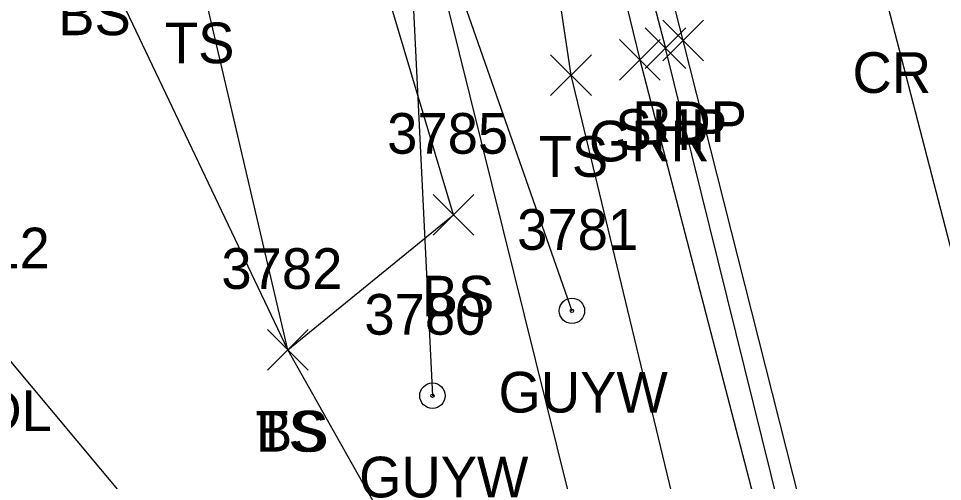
# Model space of a CAD drawing. Extents: x 1601151 to 1602912, y 499508 to 501770.
# Drawn here: x 1601576.97 to 1601622.39, y 500514.77 to 500537.54 of the extents above; entities that cross this region are included whole.
import ezdxf

# ---------------------------------------------------------------- set-up
doc = ezdxf.new("R2010")
doc.units = 0
for name, color, linetype in [('L_A', 7, 'Continuous'), ('L_I', 7, 'Continuous'), ('L_TIC', 7, 'Continuous'), ('LELB', 7, 'Continuous'), ('P_A', 7, 'Continuous'), ('P_TIC', 7, 'Continuous'), ('PET', 7, 'Continuous'), ('PRC', 7, 'Continuous'), ('PSP', 7, 'Continuous'), ('R_A', 7, 'Continuous'), ('R_TIC', 7, 'Continuous'), ('RGR', 7, 'Continuous'), ('U_A', 7, 'Continuous'), ('U_I', 7, 'Continuous'), ('UCO', 7, 'Continuous'), ('UPGW', 7, 'Continuous')]:
    doc.layers.add(name, color=color, linetype=linetype)

msp = doc.modelspace()

# ---------------------------------------------------------------- linework, layer by layer
at = {"layer": 'L_TIC'}
for points in [[(1601603.128, 500533.749), (1601605.128, 500535.749)], [(1601605.128, 500533.749), (1601603.128, 500535.749)], [(1601597.352, 500526.885), (1601599.352, 500528.885)], [(1601599.352, 500526.885), (1601597.352, 500528.885)], [(1601589.204, 500520.239), (1601591.204, 500522.239)], [(1601591.204, 500520.239), (1601589.204, 500522.239)], [(1601589.204, 500520.239), (1601591.204, 500522.239)], [(1601591.204, 500520.239), (1601589.204, 500522.239)], [(1601589.204, 500520.239), (1601591.204, 500522.239)], [(1601591.204, 500520.239), (1601589.204, 500522.239)]]:
    msp.add_lwpolyline(points, dxfattribs=at)
at = {"layer": 'LELB'}
for points in [[(1601590.204, 500521.239), (1601598.352, 500527.885), (1601592.341, 500548.06), (1601594.686, 500556.882), (1601599.278, 500565.065)], [(1601601.012, 500555.493), (1601604.128, 500534.749), (1601610.884, 500506.644), (1601622.511, 500460.26), (1601629.452, 500432.987), (1601632.351, 500420.66), (1601635.25, 500400.295), (1601642.275, 500354.375)], [(1601610.851, 500414.052), (1601618.196, 500419.726), (1601620.816, 500426.918), (1601618.381, 500441.987), (1601616.839, 500464.538), (1601599.764, 500504.302), (1601590.204, 500521.239), (1601580.484, 500541.712), (1601581.665, 500544.057), (1601586.962, 500548.393), (1601586.859, 500549.069)], [(1601590.204, 500521.239), (1601585.76, 500540.334), (1601587.677, 500545.768)], [(1601575.255, 500522.25), (1601590.139, 500504.424)]]:
    msp.add_lwpolyline(points, dxfattribs=at)
at = {"layer": 'P_TIC'}
for points in [[(1601608.643, 500535.455), (1601610.643, 500537.455)], [(1601610.643, 500535.455), (1601608.643, 500537.455)], [(1601607.777, 500535.075), (1601609.777, 500537.075)], [(1601609.777, 500535.075), (1601607.777, 500537.075)]]:
    msp.add_lwpolyline(points, dxfattribs=at)
at = {"layer": 'PET'}
for points in [[(1601609.643, 500536.455), (1601604.447, 500556.777)], [(1601976.032, 499671.31), (1601949.068, 499710.223), (1601932.497, 499734.587), (1601906.156, 499773.603), (1601879.172, 499813.541), (1601846.776, 499862.768), (1601825.901, 499896.892), (1601802.833, 499936.77), (1601785.078, 499971.146), (1601767.412, 500007.572), (1601745.411, 500058.715), (1601733.838, 500089.245), (1601721.798, 500122.71), (1601703.993, 500178.986), (1601689.714, 500228.268), (1601677.577, 500272.249), (1601666.12, 500315.053), (1601653.429, 500363.857), (1601644.592, 500397.799), (1601635.031, 500435.309), (1601622.916, 500483.995), (1601609.643, 500536.455)]]:
    msp.add_lwpolyline(points, dxfattribs=at)
at = {"layer": 'PRC'}
msp.add_lwpolyline([(1601985.389, 499677.473), (1601958.565, 499716.671), (1601942.322, 499739.604), (1601916.264, 499778.512), (1601888.678, 499819.151), (1601856.543, 499869.05), (1601836.005, 499902.112), (1601813.365, 499942.521), (1601794.976, 499977.026), (1601778.265, 500012.715), (1601755.571, 500062.845), (1601744.487, 500093.78), (1601732.766, 500126.074), (1601715.372, 500182.363), (1601700.572, 500231.277), (1601688.367, 500275.568), (1601676.784, 500317.033), (1601664.233, 500365.849), (1601655.243, 500401.01), (1601645.633, 500438.144), (1601632.995, 500486.745), (1601619.53, 500538.875)], dxfattribs=at)
at = {"layer": 'PSP'}
for points in [[(1601603.431, 500556.52), (1601608.777, 500536.075)], [(1601687.75, 500227.801), (1601675.974, 500271.579), (1601664.353, 500314.612), (1601659.493, 500332.056), (1601657.413, 500333.692), (1601650.638, 500360.121), (1601651.123, 500363.174), (1601643.244, 500397.341), (1601633.675, 500434.789), (1601621.752, 500483.668), (1601608.777, 500536.075)]]:
    msp.add_lwpolyline(points, dxfattribs=at)
at = {"layer": 'R_TIC'}
for points in [[(1601606.517, 500534.506), (1601608.517, 500536.506)], [(1601608.517, 500534.506), (1601606.517, 500536.506)]]:
    msp.add_lwpolyline(points, dxfattribs=at)
at = {"layer": 'RGR'}
msp.add_lwpolyline([(1601602.548, 500555.898), (1601607.517, 500535.506), (1601614.873, 500507.211), (1601626.042, 500459.432), (1601629.452, 500432.987)], dxfattribs=at)
at = {"layer": 'UCO'}
msp.add_lwpolyline([(1601595.966, 500546.616), (1601650.892, 500325.105)], dxfattribs=at)
at = {"layer": 'UPGW'}
for points in [[(1601595.966, 500546.616), (1601597.319, 500518.988)], [(1601595.966, 500546.616), (1601604.174, 500523.16)]]:
    msp.add_lwpolyline(points, dxfattribs=at)
for centre, radius in [((1601604.174, 500523.16), 0.625), ((1601604.174, 500523.16), 0.0833), ((1601597.319, 500518.988), 0.625), ((1601597.319, 500518.988), 0.0833)]:
    msp.add_circle(centre, radius, dxfattribs=at)

# ---------------------------------------------------------------- texts
at = {"layer": 'L_A'}
for s, p in [('BS', (1601578.925, 500536.712)), ('TS', (1601584.17, 500535.334)), ('TS', (1601602.538, 500529.749)), ('BS', (1601596.793, 500522.885)), ('WDL', (1601572.672, 500517.25)), ('TS', (1601588.613, 500516.239)), ('BS', (1601588.645, 500516.239)), ('BS', (1601588.645, 500516.239))]:
    msp.add_text(s, height=2, dxfattribs=at).set_placement(p)
at = {"layer": 'L_I'}
for s, p in [('3785', (1601595.092, 500530.885)), ('3212', (1601572.562, 500525.25)), ('3212', (1601572.562, 500525.25)), ('3782', (1601586.944, 500524.239)), ('3782', (1601586.944, 500524.239)), ('3782', (1601586.944, 500524.239))]:
    msp.add_text(s, height=2, dxfattribs=at).set_placement(p)
at = {"layer": 'P_A'}
for s, p in [('CR', (1601617.964, 500533.875)), ('RDP', (1601607.131, 500531.455)), ('SHP', (1601606.312, 500531.075))]:
    msp.add_text(s, height=2, dxfattribs=at).set_placement(p)
at = {"layer": 'R_A'}
msp.add_text('GRR', height=2, dxfattribs=at).set_placement((1601605.005, 500530.506))
at = {"layer": 'U_A'}
for p in [(1601600.567, 500518.16), (1601593.713, 500513.988)]:
    msp.add_text('GUYW', height=2, dxfattribs=at).set_placement(p)
at = {"layer": 'U_I'}
for s, p in [('3781', (1601601.481, 500526.16)), ('3780', (1601593.973, 500521.988))]:
    msp.add_text(s, height=2, dxfattribs=at).set_placement(p)

doc.saveas('drawing.dxf')
